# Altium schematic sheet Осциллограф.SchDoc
size A4; PageSetup: Record=PageOptions|CenterHorizontal=True|CenterVertical=True|PrintScale=0.96|XCorrection=1.00|YCorrection=1.00|PrintKind=0|BorderSize=5000000|LeftOffset=0|BottomOffset=0|Orientation=2|PaperLength=1000|PaperWidth=1000|Scale=100|PaperSource=7|PrintQuality=-4|MediaType=1|DitherType=10|PaperKind=A4|PrintScaleMode=1
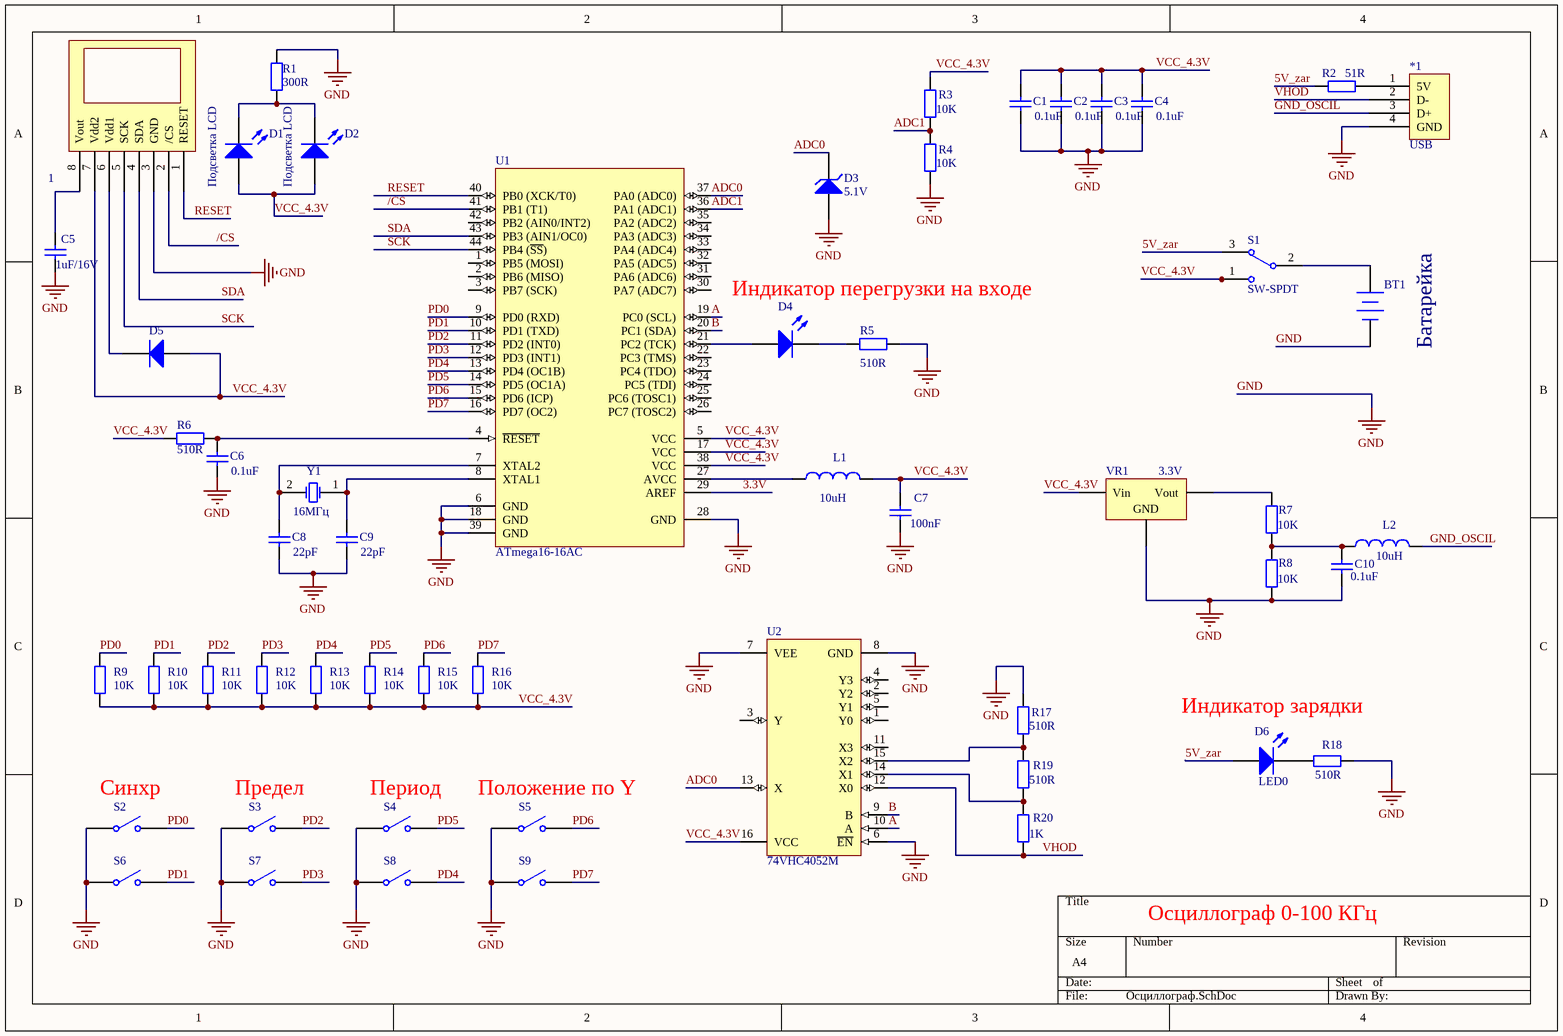
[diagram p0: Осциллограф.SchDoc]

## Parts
1  LCD  (value not drawn)
*1  USB
BT1  Батарейка  [BAT-2]
C1  value 0.1uF  [RAD-0.3]  (hidden comment: Cap)
C2  value 0.1uF  [RAD-0.3]  (hidden comment: Cap)
C3  value 0.1uF  [RAD-0.3]  (hidden comment: Cap)
C4  value 0.1uF  [RAD-0.3]  (hidden comment: Cap)
C5  value 1uF/16V  [RAD-0.3]  (hidden comment: Cap)
C6  value 0.1uF  [RAD-0.3]  (hidden comment: Cap)
C7  value 100nF  [RAD-0.3]  (hidden comment: Cap)
C8  value 22pF  [RAD-0.3]  (hidden comment: Cap)
C9  value 22pF  [RAD-0.3]  (hidden comment: Cap)
C10  value 0.1uF  [RAD-0.3]  (hidden comment: Cap)
D1  Подсветка LCD  [LED-0]
D2  Подсветка LCD  [LED-0]
D3  5.1V  [DIODE-0.7]
D4  LED0  [LED-0]  (value not drawn)
D5  Diode 1N914  [DIO7.1-3.9x1.9]  (value not drawn)
D6  LED0  [LED-0]
L1  value 10uH  [INDC1005AL]  (hidden comment: Inductor)
L2  value 10uH  [INDC1005AL]  (hidden comment: Inductor)
R1  value 300R  [AXIAL-0.4]  (hidden comment: Res2)
R2  value 51R  [AXIAL-0.4]  (hidden comment: Res2)
R3  value 10K  [AXIAL-0.4]  (hidden comment: Res2)
R4  value 10K  [AXIAL-0.4]  (hidden comment: Res2)
R5  value 510R  [AXIAL-0.4]  (hidden comment: Res2)
R6  value 510R  [AXIAL-0.4]  (hidden comment: Res2)
R7  value 10K  [AXIAL-0.4]  (hidden comment: Res2)
R8  value 10K  [AXIAL-0.4]  (hidden comment: Res2)
R9  value 10K  [AXIAL-0.4]  (hidden comment: Res2)
R10  value 10K  [AXIAL-0.4]  (hidden comment: Res2)
R11  value 10K  [AXIAL-0.4]  (hidden comment: Res2)
R12  value 10K  [AXIAL-0.4]  (hidden comment: Res2)
R13  value 10K  [AXIAL-0.4]  (hidden comment: Res2)
R14  value 10K  [AXIAL-0.4]  (hidden comment: Res2)
R15  value 10K  [AXIAL-0.4]  (hidden comment: Res2)
R16  value 10K  [AXIAL-0.4]  (hidden comment: Res2)
R17  value 510R  [AXIAL-0.4]  (hidden comment: Res2)
R18  value 510R  [AXIAL-0.4]  (hidden comment: Res2)
R19  value 510R  [AXIAL-0.4]  (hidden comment: Res2)
R20  value 1K  [AXIAL-0.4]  (hidden comment: Res2)
S1  SW-SPDT  [TL36WW15050]
S2  SW-SPST  [SPST-2]  (value not drawn)
S3  SW-SPST  [SPST-2]  (value not drawn)
S4  SW-SPST  [SPST-2]  (value not drawn)
S5  SW-SPST  [SPST-2]  (value not drawn)
S6  SW-SPST  [SPST-2]  (value not drawn)
S7  SW-SPST  [SPST-2]  (value not drawn)
S8  SW-SPST  [SPST-2]  (value not drawn)
S9  SW-SPST  [SPST-2]  (value not drawn)
U1  ATmega16-16AC  [44A_N]
U2  74VHC4052M  [M16A_N]
VR1  3.3V  [TO254P1510-3_4N]
Y1  16МГц  [BCY-W2/D3.1]

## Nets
GND: 1.3(GND) *1.4(GND) BT1.2(-) C1.1 C2.1 C3.1 C4.1 C5.1 C7.1 C8.1 C9.1 C10.1 D3.1(A) R1.2 R4.1 R5.2 R8.2 R17.2 R18.2 S2.1(COMMON) S3.1(COMMON) S4.1(COMMON) S5.1(COMMON) S6.1(COMMON) S7.1(COMMON) S8.1(COMMON) S9.1(COMMON) U1.6(GND) U1.18(GND) U1.28(GND) U1.39(GND) U2.6(~{EN}) U2.7(VEE) U2.8(GND) VR1.2(GND)
3.3V: U1.29(AREF)
5V_zar: D6.1(A) R2.1 S1.3
/CS: 1.2(/CS) U1.41(PB1_(T1))
A: U1.19(PC0_(SCL)) U2.10(A)
ADC0: D3.2(K) U1.37(PA0_(ADC0)) U2.13(X)
ADC1: R3.1 R4.2 U1.36(PA1_(ADC1))
B: U1.20(PC1_(SDA)) U2.9(B)
GND_OSCIL: *1.3(D+) L2.2
PD0: R9.2 S2.2(NO) U1.9(PD0_(RXD))
PD1: R10.2 S6.2(NO) U1.10(PD1_(TXD))
PD2: R11.2 S3.2(NO) U1.11(PD2_(INT0))
PD3: R12.2 S7.2(NO) U1.12(PD3_(INT1))
PD4: R13.2 S8.2(NO) U1.13(PD4_(OC1B))
PD5: R14.2 S4.2(NO) U1.14(PD5_(OC1A))
PD6: R15.2 S5.2(NO) U1.15(PD6_(ICP))
PD7: R16.2 S9.2(NO) U1.16(PD7_(OC2))
RESET: 1.1(RESET) U1.40(PB0_(XCK/T0))
SCK: 1.5(SCK) U1.44(PB4_(~{SS}))
SDA: 1.4(SDA) U1.43(PB3_(AIN1/OC0))
VCC_4.3V: 1.7(Vdd2) C1.2 C2.2 C3.2 C4.2 C7.2 D1.1(A) D2.1(A) D5.1(A) L1.2 R3.2 R6.2 R9.1 R10.1 R11.1 R12.1 R13.1 R14.1 R15.1 R16.1 S1.1 U1.5(VCC) U1.17(VCC) U1.38(VCC) U2.16(VCC) VR1.1(Vin)
VHOD: *1.2(D-) R20.1 U2.12(X0)
Net1_6: 1.6(Vdd1) D5.2(K)
Net1_8: 1.8(Vout) C5.2
Net*1_1: *1.1(5V) R2.2
NetBT1_1: BT1.1(+) S1.2
NetC6_2: C6.2 R6.1 U1.4(~{RESET})
NetC8_2: C8.2 U1.7(XTAL2) Y1.2(OSC2)
NetC9_2: C9.2 U1.8(XTAL1) Y1.1(OSC1)
NetC10_2: C10.2 L2.1 R7.1 R8.1
NetD1_2: D1.2(K) D2.2(K) R1.1
NetD4_1: D4.1(A) U1.21(PC2_(TCK))
NetD4_2: D4.2(K) R5.1
NetD6_2: D6.2(K) R18.1
NetL1_1: L1.1 U1.27(AVCC)
NetR7_2: R7.2 VR1.3(Vout)
NetR17_1: R17.1 R19.2 U2.15(X2)
NetR19_1: R19.1 R20.2 U2.14(X1)

Not connected (* = marked no-connect by the designer): C6 1; U1 1(PB5_(MOSI)) 2(PB6_(MISO)) 3(PB7_(SCK)) 22(PC3_(TMS)) 23(PC4_(TDO)) 24(PC5_(TDI)) 25(PC6_(TOSC1)) 26(PC7_(TOSC2)) 30(PA7_(ADC7)) 31(PA6_(ADC6)) 32(PA5_(ADC5)) 33(PA4_(ADC4)) 34(PA3_(ADC3)) 35(PA2_(ADC2)) 42(PB2_(AIN0/INT2)); U2 1(Y0) 2(Y2) 3(Y) 4(Y3) 5(Y1) 11(X3)

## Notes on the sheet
- Индикатор перегрузки на входе
- Индикатор зарядки
- (near S2) Синхр
- (near S3) Предел
- (near S4) Период
- (near S5) Положение по Y
- Осциллограф 0-100 КГц
- Labels drawn without touching a wire or pin: GND

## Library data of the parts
BT1 = Battery: Multicell Battery
C1-C10 = Cap: Capacitor
D1 D2 D4 D6 = LED0: Typical INFRARED GaAs LED
D3 = D Zener: Zener Diode
D5 = Diode 1N914: High Conductance Fast Diode
L1 L2 = Inductor: Code_IEC: 1005
R1-R20 = Res2: Resistor
S1 = SW-SPDT: SPDT Subminiature Toggle Switch, Right Angle Mounting, Vertical Actuation
S2-S9 = SW-SPST: Single-Pole, Single-Throw Switch
U1 = ATmega16-16AC: 8-Bit AVR Microcontroller with 16K Bytes of In-System Programmable Flash Memory
U2 = 74VHC4052M: Dual 4-Channel Analog Multiplexer
VR1 = Volt Reg: Voltage Regulator
Y1 = XTAL: Crystal Oscillator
